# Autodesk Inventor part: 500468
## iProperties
Created: 2007-11
Part Number: 500468
Document SubType Name: Modeling
Designer: TH
Density: 1.32 g/cm^3
Mass: 22.8369 g
Surface Area: 82.2825 cm^2
Volume: 17.3007 cm^3
Material: Polyaryletherketone Resin
Description: BELL CRANK SIDE HANDLE
Component Category: Side Component
Author: TH
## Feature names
1. Extrusion1
2. Fillet1
3. Fillet2
4. Fillet3
5. Fillet4
6. Fillet5
7. Extrusion2
8. Fillet6
9. Extrusion3
10. Extrusion4
11. Chamfer1
12. Fillet7
13. Fillet8
14. Fillet9
15. Fillet10
16. Fillet11
17. Extrusion5
18. Extrusion6
19. Extrusion7
20. Fillet12
21. Fillet13
22. Revolution1
23. Extrusion8
24. Extrusion9
25. Fillet14
26. Fillet17
27. Extrusion10
28. Circular Pattern2
29. Revolution2
30. Fillet16
31. Fillet18
32. Fillet19
